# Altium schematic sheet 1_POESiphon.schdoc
size 309 x 223 mm; Symbol: Sheet-Symbol_A4; Device: Sheet-Symbol_A4; @Project Name: V2 - ODrive Rev Motor Module; @Page Count: 5; @Update Date: 2024-12-31; @Create Date: 2024-12-04; @Schematic Name: Schematic-A; @Page No: 1; @Page Name: POESiphon; Company: EasyEDA.com; Reviewed: EasyEDA; Version: V0.1; Page Size: A4; Part Number: JLCPCB-002; Drawn: EasyEDA; @Board Name: BaseModule; @Create Time: 20:02:26; @Update Time: 16:24:46
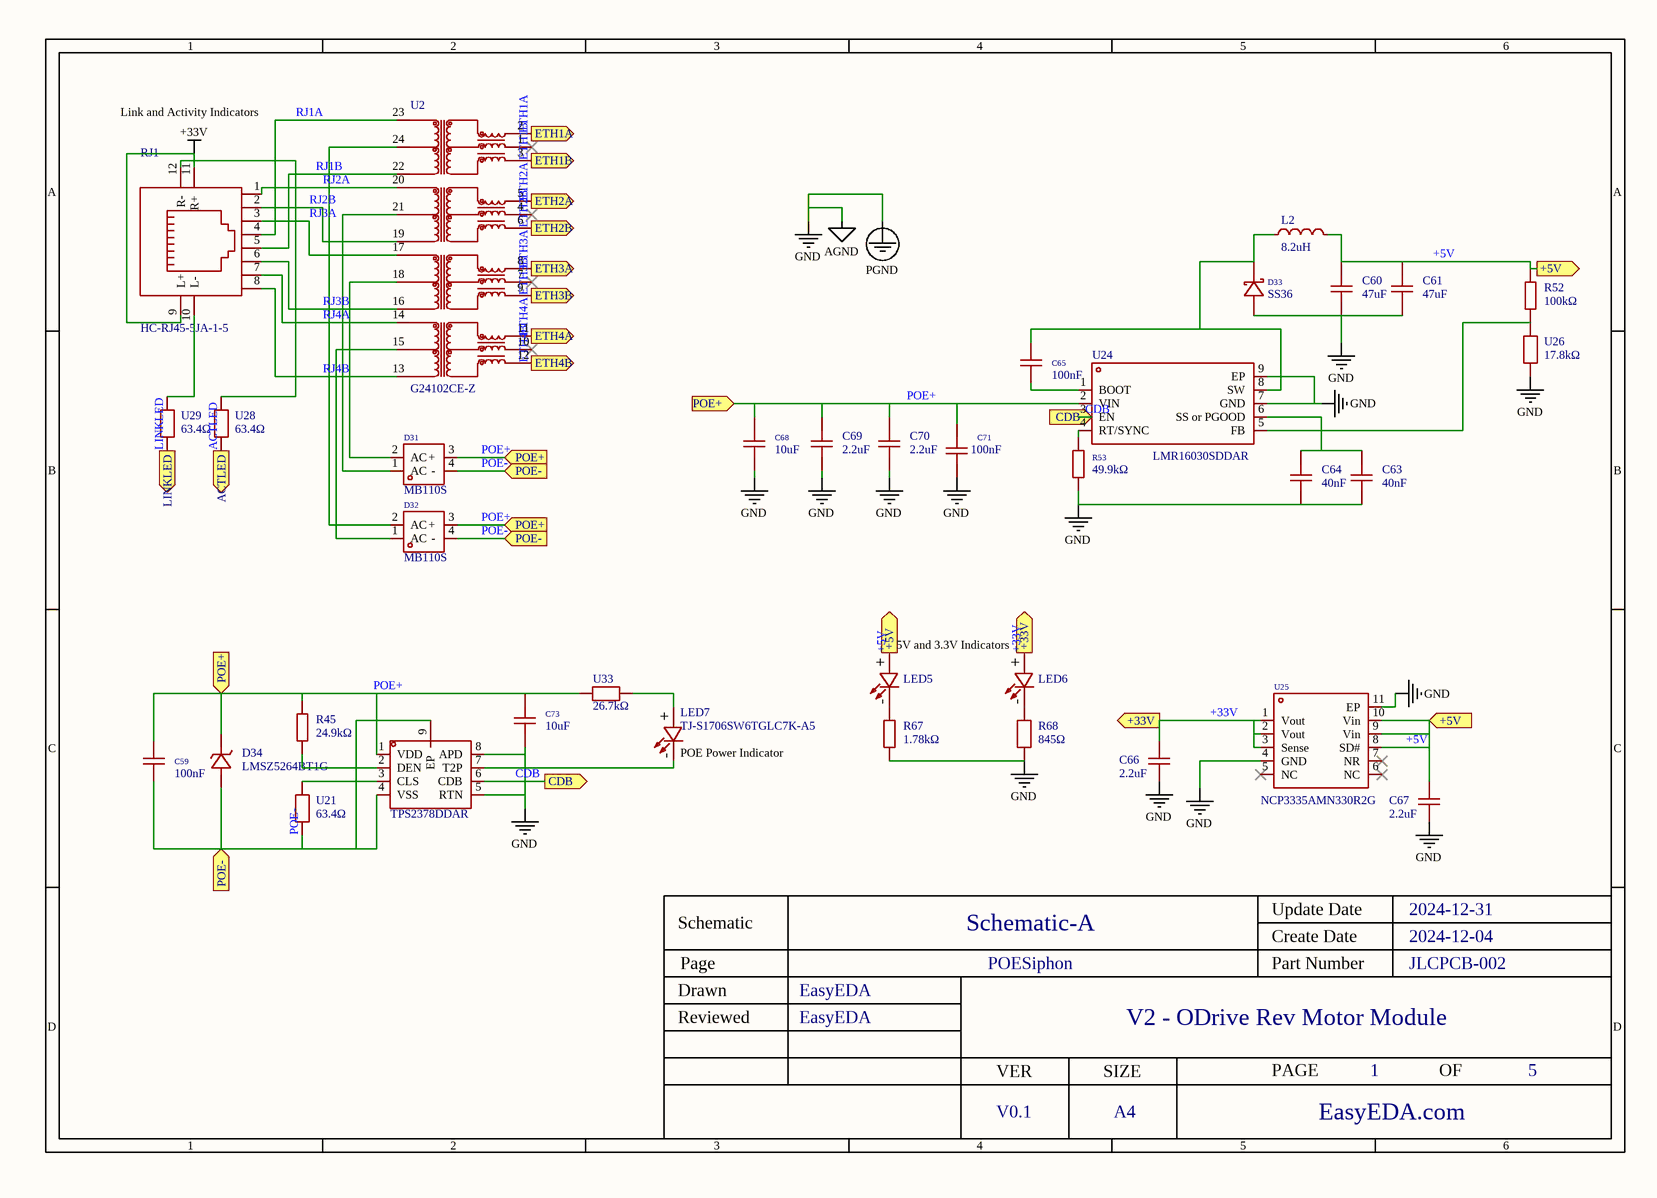
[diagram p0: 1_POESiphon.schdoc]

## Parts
C59  100nF  [C0805]
C60  47uF  [C1210]
C61  47uF  [C1210]
C63  40nF  [C0805]
C64  40nF  [C0805]
C65  100nF  [C0805]
C66  2.2uF  [C0603]
C67  2.2uF  [C0603]
C68  10uF  [C1210]
C69  2.2uF  [C1206]
C70  2.2uF  [C1206]
C71  100nF  [C0603]
C73  10uF  [C1210]
D31  MB110S  [MBS_L4.7-W4.0-P2.50-LS7.0-BL]
D32  MB110S  [MBS_L4.7-W4.0-P2.50-LS7.0-BL]
D33  SS36  [SMA_L4.4-W2.6-LS5.0-RD]
D34  LMSZ5264BT1G  [SOD-123_L2.7-W1.6-LS3.7-RD-1]
L2  8.2uH  [IND-SMD_L7.0-W6.6_FXL0630]
LED5  TJ-S1706SW6TGLC7K-A5  [LED-SMD_L1.7-W0.6-RD_GREEN]  (value not drawn)
LED6  TJ-S1706SW6TGLC7K-A5  [LED-SMD_L1.7-W0.6-RD_GREEN]  (value not drawn)
LED7  TJ-S1706SW6TGLC7K-A5  [LED-SMD_L1.7-W0.6-RD_GREEN]
R45  24.9kΩ  [R0603]
R52  100kΩ  [R0402]
R53  49.9kΩ  [R0603]
R67  1.78kΩ  [R0402]
R68  845Ω  [R0402]
RJ1  HC-RJ45-5JA-1-5  [RJ45-TH_HC-RJ45-5JA-1-5]
U2  G24102CE-Z  [SMD-24_L18.2-W12.2-P1.27_G24102CE-Z]
U17  TPS2378DDAR  [SO-8_L4.9-W3.9-P1.27-LS6.0-BL-EP]
U21  63.4Ω  [R0805]
U24  LMR16030SDDAR  [SO-8_L4.9-W3.9-P1.27-LS6.0-BL-EP]
U25  NCP3335AMN330R2G  [DFN-10_L3.0-W3.0-P0.50-BL-EP-1]
U26  17.8kΩ  [R0603]
U28  63.4Ω  [R0805]
U29  63.4Ω  [R0805]
U33  26.7kΩ  [R0603]

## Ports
+5V (in), +5V (out), +33V (out), ACTLED (out), CDB (in), CDB (out), ETH1A (out), ETH1B (out), ETH2A (out), ETH2B (out), ETH3A (out), ETH3B (out), ETH4A (out), ETH4B (out), LINKLED (out), POE+ (in), POE- (in)

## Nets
+33V: C66.2 LED6.2 RJ1.9(L+) RJ1.11(R+) U25.1(Vout) U25.2(Vout) U25.3(Sense) ; port +33V
AGND: C60.1 C61.1 C63.1 C64.1 C66.1 C67.1 C68.1 C69.1 C70.1 C71.1 C73.1 D33.2(A) R53.1 R67.1 R68.1 U17.5(RTN) U17.8(APD) U24.7(GND) U24.9(EP) U25.4(GND) U25.11(EP) U26.1  [also labelled GND, PGND]
+5V: C60.2 C61.2 C67.2 L2.2 LED5.2 R52.2 U25.8(SD#) U25.9(Vin) U25.10(Vin) ; port +5V
ACTLED: U28.1 ; port ACTLED
CDB: U17.6(CDB) U24.3(EN) ; port CDB
ETH1A: U2.2 ; port ETH1A
ETH1B: U2.3 ; port ETH1B
ETH2A: U2.5 ; port ETH2A
ETH2B: U2.6 ; port ETH2B
ETH3A: U2.8 ; port ETH3A
ETH3B: U2.9 ; port ETH3B
ETH4A: U2.11 ; port ETH4A
ETH4B: U2.12 ; port ETH4B
LINKLED: U29.1 ; port LINKLED
POE+: C59.1 C68.2 C69.2 C70.2 C71.2 C73.2 D31.3(+) D32.3(+) D34.1(C) R45.2 U17.1(VDD) U24.2(VIN) U33.1 ; port POE+
POE-: C59.2 D31.4(-) D32.4(-) D34.2(A) U17.4(VSS) U17.9(EP) U21.1 ; port POE-
RJ1A: RJ1.4 U2.23
RJ1B: RJ1.5 U2.22
RJ2A: RJ1.1 U2.20
RJ2B: RJ1.2 U2.19
RJ3A: RJ1.3 U2.17
RJ3B: RJ1.6 U2.16
RJ4A: RJ1.7 U2.14
RJ4B: RJ1.8 U2.13
NetC63_2: C63.2 C64.2 U24.6(SS_or_PGOOD)
NetC65_1: C65.1 D33.1(K) L2.1 U24.8(SW)
NetC65_2: C65.2 U24.1(BOOT)
NetD31_1: D31.1(AC) U2.21
NetD31_2: D31.2(AC) U2.18
NetD32_1: D32.1(AC) U2.15
NetD32_2: D32.2(AC) U2.24
NetLED5_1: LED5.1 R67.2
NetLED6_1: LED6.1 R68.2
NetLED7_1: LED7.1 U17.7(T2P)
NetLED7_2: LED7.2 U33.2
NetR45_1: R45.1 U17.2(DEN)
NetR52_1: R52.1 U24.5(FB) U26.2
NetR53_2: R53.2 U24.4(RT/SYNC)
NetRJ1_10: RJ1.10(L-) U29.2
NetRJ1_12: RJ1.12(R-) U28.2
NetU17_3: U17.3(CLS) U21.2

Not connected (* = marked no-connect by the designer): U2 1* 4* 7* 10*; U25 5(NC)* 6(NC)* 7(NR)*

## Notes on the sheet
- Link and Activity Indicators
- 5V and 3.3V Indicators
- (near LED7) POE Power Indicator

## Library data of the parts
C59 C65 = 0805B104K500NT: Manufacturer: FH(风华); Add into BOM: yes; Tolerance: ±10%
C60 C61 = CS3225X7R476K160NRL: Manufacturer: SAMWHA(三和); Add into BOM: yes; Tolerance: ±10%
C63 C64 = 0805F403M500NT: Manufacturer: FH(风华); Add into BOM: yes; Tolerance: ±20%
C66 C67 = CL10A225KO8NNNC: Manufacturer: SAMSUNG(三星); Add into BOM: yes; Tolerance: ±10%
C68 C73 = FS32X106K101EGG: Manufacturer: PSA(信昌电陶); Add into BOM: yes; Tolerance: ±10%
C69 C70 = CC1206KKX7R0BB225: Manufacturer: YAGEO(国巨); Add into BOM: yes; Tolerance: ±10%
C71 = CC0603KRX7R0BB104: Manufacturer: YAGEO(国巨); Add into BOM: yes; Tolerance: ±10%
D31 D32 = MB110S_C382811: Manufacturer: 晶导微电子; Add into BOM: yes; Forward Voltage (Vf@If): 850mV@1A; Reverse Leakage Current (Ir): 200uA@100V
D33 = SS36_C727061: Manufacturer: TWGMC(台湾迪嘉); Add into BOM: yes; Diode Configuration: Single; Forward Voltage (Vf@If): 700mV@3A; Reverse Voltage (Vr): 60V; Average Rectified Current (Io): 3A; Reverse Leakage Current (Ir): 500uA@60V
D34 = LMSZ5264BT1G: Manufacturer: LRC(乐山无线电); Add into BOM: yes; Diode Configuration: Single; Zener Voltage (Nom): 60V; Reverse Leakage Current (Ir): 2.1mA; Zener Voltage (Range): 57V~63V; Power Dissipation: 500mW; Zener Impedance (Zzt): 170Ω; Tolerance: ±5%
L2 = FXL0630-8R2-M: Manufacturer: cjiang(长江微电); Add into BOM: yes; Tolerance: ±20%; Saturation Current (Isat): 6A; Type: Integrated molded inductor
LED5-LED7 = TJ-S1706SW6TGLC7K-A5: Manufacturer: TOGIALED(统佳); Add into BOM: yes; Emitted Color: Yellow Green; Forward Voltage (VF): 1.8V~2.4V; Viewing Angle: 120°; Mounting Sytle: Side sticker
R45 = 0603WAF2492T5E: Manufacturer: UNI-ROYAL(厚声); Add into BOM: yes; Tolerance: ±1%; Temperature Coefficient: ±100ppm/℃
R52 = RC0402FR-07100KL: Manufacturer: YAGEO(国巨); Add into BOM: yes; Tolerance: ±1%; Temperature Coefficient: ±100ppm/℃
R53 = 0603WAF4992T5E: Manufacturer: UNI-ROYAL(厚声); Add into BOM: yes; Tolerance: ±1%; Temperature Coefficient: ±100ppm/℃
R67 = RC0402FR-071K78L: Manufacturer: YAGEO(国巨); Add into BOM: yes; Tolerance: ±1%; Temperature Coefficient: ±100ppm/℃
R68 = RC0402FR-07845RL: Manufacturer: YAGEO(国巨); Add into BOM: yes; Tolerance: ±1%; Temperature Coefficient: ±100ppm/℃
RJ1 = HC-RJ45-5JA-1-5: Manufacturer: HCTL(华灿天禄); Add into BOM: yes; Connector Type: RJ45Receptacle; Number of Ports: 1; Shielding: Unshielded; LED: WithLED; Soldering Temperature(Max): 260℃@3S
U2 = G24102CE-Z: Manufacturer: Mentech(铭普光磁); Add into BOM: yes
U17 = TPS2378DDAR: Manufacturer: TI(德州仪器); Add into BOM: yes
U21 U28 U29 = CR0805F863R4G: Manufacturer: LIZ(丽智电子); Add into BOM: yes; Tolerance: ±1%
U24 = LMR16030SDDAR: Manufacturer: TI(德州仪器); Add into BOM: yes; Function: Step-down type; Output Type: Adjustable; Input Voltage: 4.3V~60V; Output Voltage: 800mV~50V; Output Current (Max): 3A; Switching Frequency: 2.5MHz; Synchronous Rectification: NO; Number of Outputs: 1; Topology: Step-down; Switch tube (built-in/external): 内置
U25 = NCP3335AMN330R2G: Manufacturer: onsemi(安森美); Add into BOM: yes; Output Type: 固定; Maximum Input Voltage: 16V; Output Voltage: 3.3V; MAX Output Current: 500mA; Dropout Voltage: 0.34V@(500mA); standby current: 190uA; Output Polarity: Positive electrode; Number of Outputs: 1
U26 = FRC0603F1782TS: Manufacturer: FOJAN(富捷); Add into BOM: yes; Tolerance: ±1%; Temperature Coefficient: ±100ppm/℃
U33 = FRC0603F2672TS: Manufacturer: FOJAN(富捷); Add into BOM: yes; Tolerance: ±1%; Temperature Coefficient: ±100ppm/℃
